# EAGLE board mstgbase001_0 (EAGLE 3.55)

Size 127.64 x 102.87 mm. Coordinates in mm from the lower left corner, seen from the top.
Outline: 121.92,12.86 121.92,91.91 15.88,91.91 15.88,12.86 121.92,12.86
Outline: 0,0.63 1.27,0 127,0 127.64,0.63 127.64,102.23 127,102.87 1.27,102.87 0,102.23 0,0.63
Copper layers used: 
vRestrict: area 69.9,50.8 to 94,74.9

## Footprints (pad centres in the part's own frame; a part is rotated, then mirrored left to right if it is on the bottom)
V = drill 0.914 pad 1.6 round:  -8.89,-1.27 | drill 0.914 pad 1.6 octagon:  -8.89,1.27;  -6.35,-1.27;  -6.35,1.27;  -3.81,-1.27;  -3.81,1.27;  -1.27,-1.27;  -1.27,1.27;  1.27,-1.27;  1.27,1.27;  3.81,-1.27;  3.81,1.27;  6.35,-1.27;  6.35,1.27;  8.89,-1.27;  8.89,1.27 | hole 3.302: 17.78,-0.254; -17.78,-0.254
3MM = drill 1.27 pad 3.81 octagon:  0,0;  7.62,0;  0,-5.08;  7.62,-5.08
LAIS_R = drill 1.27 pad 2.54 octagon:  -12.7,5.08;  -12.7,-2.54;  -2.54,5.08;  5.08,5.08

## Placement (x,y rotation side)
PL1  16V  [V]  not placed on the board
PL2  6_3MM  [3MM]  not placed on the board
PL3  6_3MM  [3MM]  19.68,64.14 90 top
PL4  6_3MM  [3MM]  19.68,48.89 90 top
PL5  6_3MM  [3MM]  19.68,33.66 90 top
PL6  6_3MM  [3MM]  19.68,18.41 90 top
PL7  6_3MM  [3MM]  89.53,75.56 0 top
PL8  6_3MM  [3MM]  104.14,61.59 0 top
PL9  6_3MM  [3MM]  107.95,45.72 0 top
PL10  6_3MM  [3MM]  104.14,27.3 0 top
PL11  10V  [V]  not placed on the board
PL12  6_3MM  [3MM]  not placed on the board
PL13  6_3MM  [3MM]  not placed on the board
PL14  6_3MM  [3MM]  84.45,32.38 0 top
PL15  6_3MM  [3MM]  not placed on the board
PL16  6_3MM  [3MM]  not placed on the board
REL1  Q7  [LAIS_R]  53.34,81.92 0 top
REL2  Q1  [LAIS_R]  55.24,66.04 0 top
REL3  Q0  [LAIS_R]  52.07,49.53 0 top
REL4  Q2  [LAIS_R]  52.07,34.29 0 top
REL5  Q3  [LAIS_R]  57.78,19.05 0 top
REL6  Q4  [LAIS_R]  83.19,77.47 0 top
REL7  Q5  [LAIS_R]  83.82,60.96 0 top
REL8  Q6  [LAIS_R]  81.28,46.36 0 top

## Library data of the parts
PL1 PL11 = pinh-v
PL2-PL10 PL12-PL16 REL1-REL8 = andit4at

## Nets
N$1: PL14. REL1. REL2. REL3. REL4. REL5. REL6. REL7. REL8.
N$2: PL9. REL1.
N$3: PL9. REL8.
N$4: PL7. REL7.
N$7: PL2. PL11.
N$9: PL1. REL4.
N$10: PL1. REL2.
N$11: PL10. REL3.
N$12: PL10. REL2.
N$13: PL8. REL4.
N$15: PL8. REL5.
N$16: PL7. REL6.
N$17: PL1. REL3.
N$18: PL1. REL5.
N$19: PL1. REL6.
N$20: PL1. REL7.
N$21: PL1. REL8.
N$22: PL1. REL1.
N$23: PL14. REL1. REL2. REL3. REL4. REL5. REL6. REL7. REL8.
N$24: PL1. PL5.
N$25: PL1. PL5.
N$26: PL1. PL4.
N$27: PL1. PL4.
N$28: PL1. PL3.
N$29: PL1. PL3.
N$30: PL2. PL11.
N$31: PL11. PL12.
N$32: PL11. PL12.
N$33: PL11. PL13.
N$34: PL1. PL6.
N$35: PL1. PL6.
N$36: PL11. PL13.
N$37: PL11. PL16.
N$38: PL11. PL16.
N$39: PL11. PL15.
N$40: PL11. PL15.

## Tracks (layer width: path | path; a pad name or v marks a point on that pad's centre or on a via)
N$1  (8 unrouted)
N$2  (1 unrouted)
N$3  (1 unrouted)
N$4  (1 unrouted)
N$7  (1 unrouted)
N$9  (1 unrouted)
N$10  (1 unrouted)
N$11  (1 unrouted)
N$12  (1 unrouted)
N$13  (1 unrouted)
N$15  (1 unrouted)
N$16  (1 unrouted)
N$17  (1 unrouted)
N$18  (1 unrouted)
N$19  (1 unrouted)
N$20  (1 unrouted)
N$21  (1 unrouted)
N$22  (1 unrouted)
N$23  (8 unrouted)
N$24  (1 unrouted)
N$25  (1 unrouted)
N$26  (1 unrouted)
N$27  (1 unrouted)
N$28  (1 unrouted)
N$29  (1 unrouted)
N$30  (1 unrouted)
N$31  (1 unrouted)
N$32  (1 unrouted)
N$33  (1 unrouted)
N$34  (1 unrouted)
N$35  (1 unrouted)
N$36  (1 unrouted)
N$37  (1 unrouted)
N$38  (1 unrouted)
N$39  (1 unrouted)
N$40  (1 unrouted)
